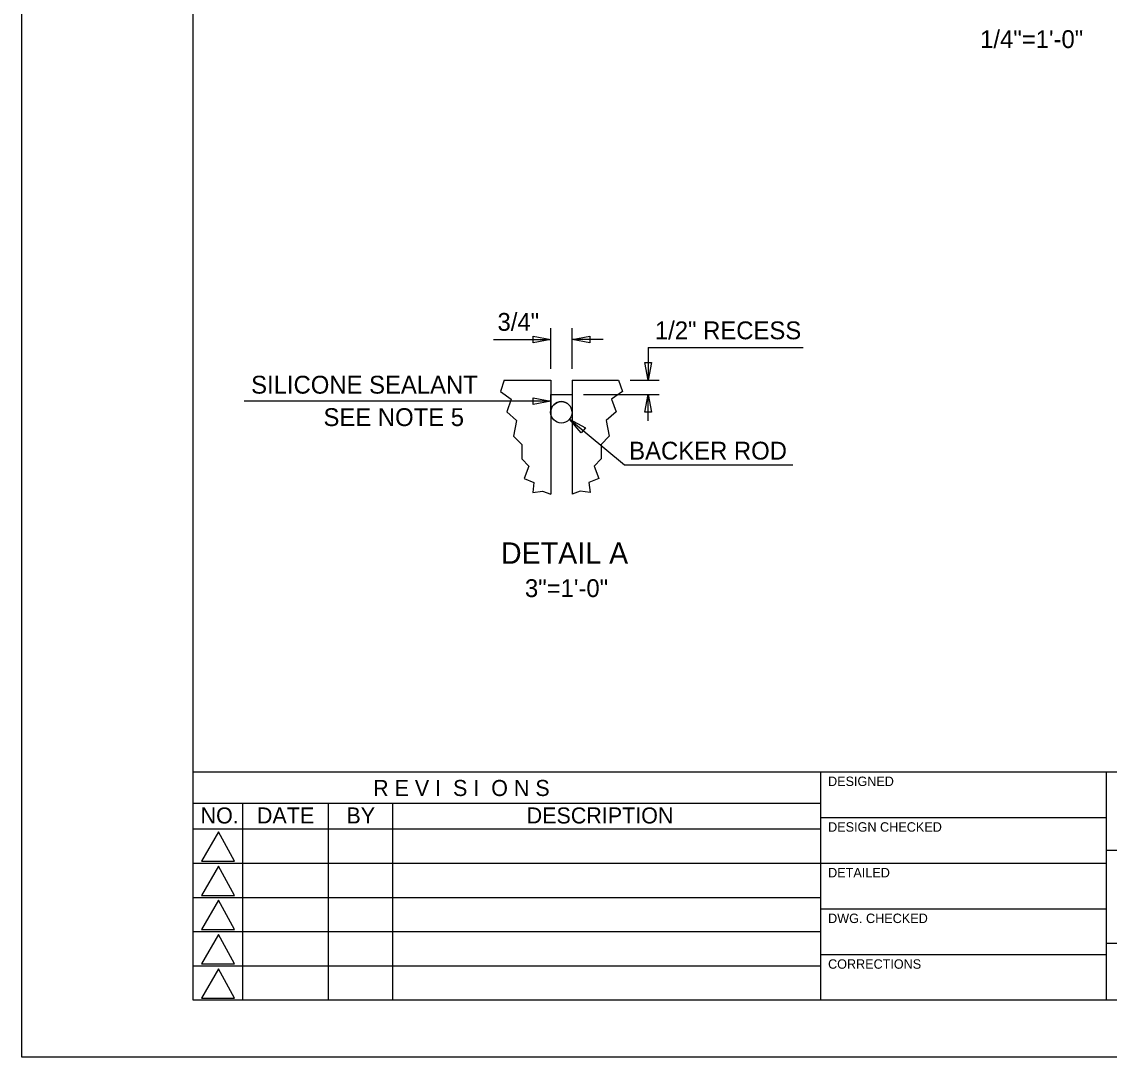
# Model space of a CAD drawing. Extents: x 0 to 68, y 0 to 47.1.
# Drawn here: x 0 to 19.05, y 0 to 18.13 of the extents above; entities that cross this region are included whole.
import ezdxf

# ---------------------------------------------------------------- set-up
doc = ezdxf.new("R2010")
doc.units = 0
for name, color, linetype in [('BORDER_ANNO_Cutsheet', 7, 'Continuous'), ('BRDG_ANNO_Anno-Sheet', 7, 'Continuous'), ('BRDG_ANNO_General-Notes', 7, 'Continuous'), ('BRDG_BASE_Active-Point', 7, 'Continuous'), ('BRDG_BASE_Obj-Line', 7, 'Continuous'), ('BRDG_BASE_Phtline', 7, 'Continuous'), ('BRDG_BASE_Rebar', 7, 'Continuous')]:
    doc.layers.add(name, color=color, linetype=linetype)

msp = doc.modelspace()

# ---------------------------------------------------------------- linework, layer by layer
at = {"layer": 'BORDER_ANNO_Cutsheet'}
msp.add_lwpolyline([(0, 44), (68, 44), (68, 0), (0, 0)], close=True, dxfattribs=at)
at = {"layer": 'BRDG_ANNO_Anno-Sheet'}
for p, q in [((3, 5), (38.5, 5)), ((14, 1), (14, 5)), ((19, 1), (19, 5)), ((3, 4.45), (14, 4.45)), ((3.875, 1), (3.875, 4.45)), ((5.375, 1), (5.375, 4.45)), ((6.5, 1), (6.5, 4.439)), ((14, 4.2), (19, 4.2)), ((2.995, 4), (14, 4)), ((19, 3.625), (23, 3.625)), ((2.995, 3.4), (14, 3.4)), ((14, 3.4), (19, 3.4)), ((2.995, 2.8), (14, 2.8)), ((14, 2.6), (19, 2.6)), ((2.995, 2.2), (14, 2.2)), ((19, 2), (23, 2)), ((14, 1.8), (19, 1.8)), ((2.995, 1.6), (14, 1.6))]:
    msp.add_line(p, q, dxfattribs=at)
msp.add_lwpolyline([(3, 43), (67, 43), (67, 1), (3, 1)], close=True, dxfattribs=at)
for points in [[(3.445, 3.949), (3.149, 3.435), (3.729, 3.435), (3.445, 3.949)], [(3.445, 3.349), (3.149, 2.835), (3.729, 2.835), (3.445, 3.349)], [(3.445, 2.749), (3.149, 2.235), (3.729, 2.235), (3.445, 2.749)], [(3.445, 2.149), (3.149, 1.635), (3.729, 1.635), (3.445, 2.149)], [(3.445, 1.549), (3.149, 1.035), (3.729, 1.035), (3.445, 1.549)]]:
    msp.add_lwpolyline(points, dxfattribs=at)
at = {"layer": 'BRDG_ANNO_General-Notes'}
for p, q in [((9.266, 12.054), (9.266, 12.767)), ((9.641, 12.054), (9.641, 12.767)), ((8.956, 12.512), (8.956, 12.628)), ((8.956, 12.628), (9.266, 12.57)), ((9.641, 12.57), (9.951, 12.628)), ((9.951, 12.628), (9.951, 12.512)), ((8.266, 12.57), (9.266, 12.57)), ((9.266, 12.57), (8.956, 12.512)), ((10.187, 12.57), (9.641, 12.57)), ((9.951, 12.512), (9.641, 12.57)), ((10.971, 12.427), (10.971, 11.857)), ((10.971, 12.427), (13.691, 12.427)), ((10.913, 12.167), (11.029, 12.167)), ((10.971, 11.857), (10.913, 12.167)), ((11.029, 12.167), (10.971, 11.857)), ((10.658, 11.857), (11.168, 11.857)), ((9.266, 11.488), (3.894, 11.488)), ((8.956, 11.43), (8.956, 11.546)), ((8.956, 11.546), (9.266, 11.488)), ((9.266, 11.488), (8.956, 11.43)), ((9.838, 11.607), (11.168, 11.607)), ((10.913, 11.297), (10.971, 11.607)), ((10.971, 11.148), (10.971, 11.607)), ((10.971, 11.607), (11.029, 11.297)), ((11.029, 11.297), (10.913, 11.297)), ((9.598, 11.175), (10.561, 10.376)), ((9.799, 10.933), (9.598, 11.175)), ((9.598, 11.175), (9.873, 11.022)), ((9.873, 11.022), (9.799, 10.933)), ((10.561, 10.376), (13.508, 10.376))]:
    msp.add_line(p, q, dxfattribs=at)
at = {"layer": 'BRDG_BASE_Active-Point'}
msp.add_line((0, 0), (0, 0), dxfattribs=at)
at = {"layer": 'BRDG_BASE_Obj-Line'}
for p, q in [((8.453, 11.857), (9.266, 11.857)), ((9.266, 11.857), (9.266, 9.863)), ((9.641, 11.857), (9.641, 9.863)), ((9.641, 11.857), (10.453, 11.857))]:
    msp.add_line(p, q, dxfattribs=at)
for points in [[(8.453, 11.857), (8.384, 11.657), (8.576, 11.525), (8.496, 11.302), (8.669, 11.15), (8.617, 10.875), (8.759, 10.734), (8.759, 10.482), (8.882, 10.35), (8.8, 10.137), (8.972, 10.065), (8.952, 9.893), (9.124, 9.914), (9.266, 9.863)], [(10.453, 11.857), (10.523, 11.657), (10.33, 11.525), (10.41, 11.302), (10.238, 11.15), (10.289, 10.875), (10.148, 10.734), (10.148, 10.482), (10.025, 10.35), (10.107, 10.137), (9.935, 10.065), (9.955, 9.893), (9.783, 9.914), (9.641, 9.863)]]:
    msp.add_lwpolyline(points, dxfattribs=at)
at = {"layer": 'BRDG_BASE_Phtline'}
for p, q in [((9.266, 11.295), (9.266, 11.607)), ((9.266, 11.607), (9.641, 11.607)), ((9.641, 11.607), (9.641, 11.295))]:
    msp.add_line(p, q, dxfattribs=at)
msp.add_arc((9.453, 11.295), 0.188, 0, 180, dxfattribs=at)
at = {"layer": 'BRDG_BASE_Rebar'}
msp.add_circle((9.453, 11.295), 0.188, dxfattribs=at)

# ---------------------------------------------------------------- texts
at = {"layer": 'BRDG_ANNO_Anno-Sheet'}
for s, height, p in [('R E V I  S I  O N S', 0.28125, (6.155, 4.575)), ('DESIGNED', 0.165, (14.125, 4.75)), ('NO.', 0.2812, (3.133, 4.094)), ('DATE', 0.2812, (4.12, 4.094)), ('BY', 0.2812, (5.688, 4.094)), ('DESCRIPTION', 0.28125, (8.845, 4.094)), ('DESIGN CHECKED', 0.16562, (14.125, 3.95)), ('DETAILED', 0.1656, (14.125, 3.15)), ('DWG. CHECKED', 0.16562, (14.125, 2.35)), ('CORRECTIONS', 0.165, (14.125, 1.55))]:
    msp.add_text(s, height=height, dxfattribs=at).set_placement(p)
at = {"layer": 'BRDG_ANNO_General-Notes'}
for s, height, p in [('1/4"=1\'-0"', 0.3125, (16.789, 17.674)), ('3/4"', 0.3125, (8.334, 12.722)), ('1/2" RECESS', 0.3125, (11.091, 12.574)), ('SILICONE SEALANT', 0.3125, (4.018, 11.622)), ('SEE NOTE 5', 0.3125, (5.286, 11.054)), ('BACKER ROD', 0.3125, (10.641, 10.467)), ('DETAIL A', 0.375, (8.394, 8.642)), ('3"=1\'-0"', 0.3125, (8.815, 8.059))]:
    msp.add_text(s, height=height, dxfattribs=at).set_placement(p)

doc.saveas('drawing.dxf')
